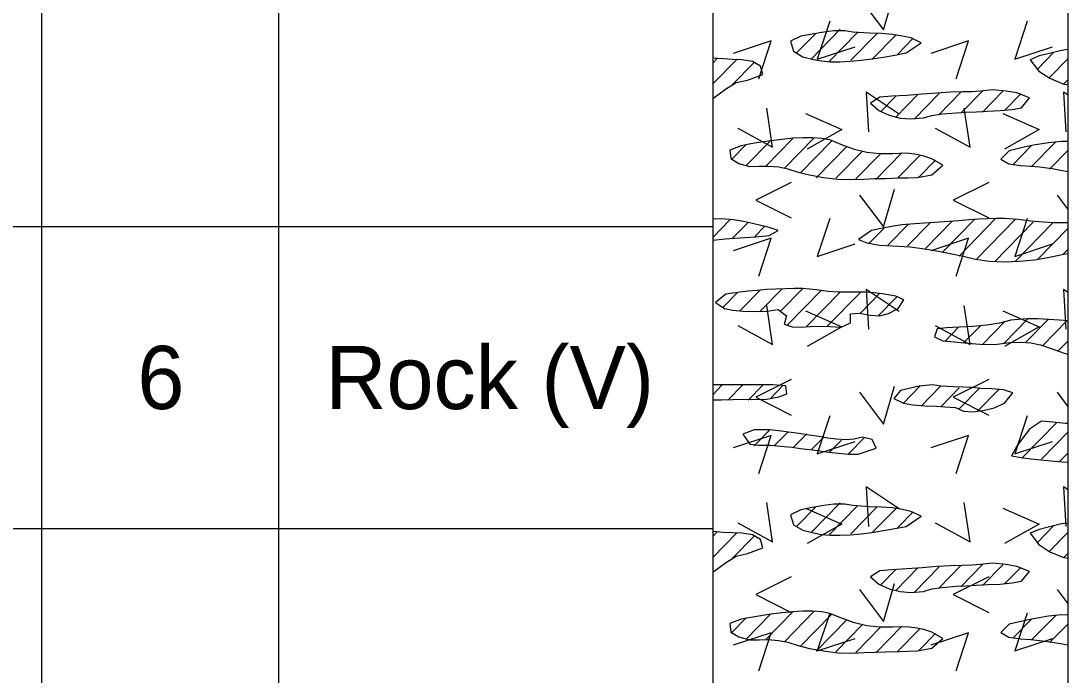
# Model space of a CAD drawing. Extents: x -0.01 to 0.83, y -0.63 to 1.27.
# Drawn here: x 0.7228 to 0.8333, y 0.1679 to 0.237 of the extents above; entities that cross this region are included whole.
import ezdxf

# ---------------------------------------------------------------- set-up
doc = ezdxf.new("R2010")
doc.units = 0

msp = doc.modelspace()

# ---------------------------------------------------------------- linework, layer by layer
for points in [[(0, 0), (0.83333, 0), (0.83333, 1.275), (0, 1.275)], [(0, 0), (0.83333, 0), (0.83333, 1.275), (0, 1.275)], [(0, 0), (0.83333, 0), (0.83333, 1.275), (0, 1.275)], [(0, 0), (0.83333, 0), (0.83333, 1.275), (0, 1.275)], [(0, 0), (0.83333, 0), (0.83333, 1.275), (0, 1.275)], [(0.81233, 0.23565), (0.81063, 0.23577), (0.80977, 0.23591), (0.8086, 0.23591), (0.80755, 0.23577), (0.80632, 0.23557), (0.80513, 0.23533), (0.80403, 0.23481), (0.80436, 0.23375), (0.80536, 0.23318), (0.80647, 0.23288), (0.8073, 0.23273), (0.80824, 0.23265), (0.80926, 0.23264), (0.81035, 0.2327), (0.81149, 0.2328), (0.81267, 0.23295), (0.81386, 0.23313), (0.81506, 0.23334), (0.81625, 0.23358), (0.81783, 0.23466), (0.81673, 0.23516), (0.81585, 0.23536), (0.8148, 0.23552), (0.81361, 0.23562)], [(0.83265, 0.23384), (0.83136, 0.23353), (0.83028, 0.23326), (0.82934, 0.23286), (0.83026, 0.23166), (0.83142, 0.2309), (0.83279, 0.23032), (0.83333, 0.23022), (0.83333, 0.23393)], [(0.79583, 0.22875), (0.79719, 0.22974), (0.79831, 0.23044), (0.79951, 0.23071), (0.80111, 0.23131), (0.80086, 0.23219), (0.80002, 0.23267), (0.79889, 0.23286), (0.79791, 0.23289), (0.79694, 0.23295), (0.79583, 0.23303)], [(0.82537, 0.22969), (0.82408, 0.22954), (0.82319, 0.22948), (0.82214, 0.22946), (0.82091, 0.22942), (0.81947, 0.22933), (0.81792, 0.22921), (0.81632, 0.22909), (0.81475, 0.229), (0.81348, 0.2289), (0.81247, 0.22826), (0.81337, 0.22749), (0.81444, 0.22699), (0.81561, 0.2267), (0.81675, 0.2266), (0.81807, 0.22671), (0.81896, 0.22698), (0.82003, 0.22713), (0.82157, 0.22725), (0.82253, 0.22731), (0.82362, 0.22737), (0.82483, 0.22743), (0.82618, 0.22749), (0.82745, 0.2276), (0.82842, 0.22778), (0.82927, 0.22883), (0.82791, 0.22935), (0.82679, 0.22955)], [(0.79885, 0.22378), (0.79763, 0.22332), (0.79773, 0.22242), (0.79859, 0.2219), (0.7997, 0.2216), (0.80074, 0.22161), (0.80165, 0.22163), (0.80281, 0.22154), (0.80377, 0.22134), (0.80486, 0.22099), (0.80606, 0.22069), (0.80751, 0.22042), (0.80905, 0.22023), (0.81052, 0.2202), (0.81177, 0.22026), (0.81289, 0.2203), (0.81408, 0.22033), (0.81553, 0.22037), (0.81642, 0.2204), (0.81745, 0.22043), (0.81897, 0.22071), (0.82011, 0.22174), (0.81896, 0.22241), (0.8181, 0.22268), (0.81717, 0.22287), (0.81626, 0.22298), (0.81479, 0.22292), (0.81343, 0.22292), (0.8121, 0.22307), (0.8108, 0.22338), (0.80953, 0.22384), (0.8082, 0.22439), (0.80736, 0.22455), (0.8064, 0.22462), (0.80536, 0.22462), (0.80427, 0.22456), (0.80314, 0.22445), (0.80201, 0.22431), (0.8009, 0.22414), (0.79984, 0.22396)], [(0.83263, 0.22423), (0.83126, 0.22409), (0.82969, 0.22382), (0.82883, 0.22365), (0.82712, 0.22324), (0.82623, 0.22237), (0.82708, 0.22188), (0.82831, 0.22169), (0.82941, 0.22163), (0.83033, 0.22154), (0.83165, 0.22136), (0.83253, 0.22121), (0.83333, 0.22107), (0.83333, 0.22422)], [(0.79583, 0.21382), (0.79715, 0.21393), (0.79814, 0.21401), (0.79922, 0.21408), (0.80039, 0.21417), (0.80179, 0.21429), (0.80275, 0.21481), (0.80179, 0.21515), (0.80091, 0.21536), (0.80003, 0.21558), (0.79909, 0.21579), (0.79803, 0.21595), (0.79677, 0.21605), (0.79583, 0.21603)], [(0.82816, 0.21158), (0.82978, 0.21174), (0.83137, 0.212), (0.8329, 0.21231), (0.83333, 0.21241), (0.83333, 0.21565), (0.83295, 0.21562), (0.83188, 0.21564), (0.83071, 0.21569), (0.82938, 0.2158), (0.82807, 0.21597), (0.82662, 0.21609), (0.82576, 0.21609), (0.82484, 0.21606), (0.82387, 0.21601), (0.82286, 0.21594), (0.82182, 0.21586), (0.82077, 0.21578), (0.81973, 0.2157), (0.81872, 0.21562), (0.81715, 0.21552), (0.81579, 0.21543), (0.81491, 0.2153), (0.81357, 0.21502), (0.8126, 0.21481), (0.81121, 0.21389), (0.8121, 0.21353), (0.81345, 0.21329), (0.81479, 0.21319), (0.81668, 0.21309), (0.81818, 0.21289), (0.81905, 0.21275), (0.82, 0.21257), (0.82107, 0.21235), (0.82225, 0.2121), (0.82357, 0.21181), (0.82501, 0.21158), (0.82656, 0.21151)], [(0.79708, 0.20659), (0.79794, 0.20642), (0.79904, 0.2063), (0.80028, 0.20627), (0.80156, 0.20632), (0.80274, 0.20648), (0.80361, 0.20582), (0.80338, 0.20492), (0.80422, 0.20465), (0.80517, 0.20463), (0.80613, 0.20469), (0.8072, 0.20472), (0.80818, 0.20469), (0.80939, 0.20461), (0.81037, 0.20508), (0.81038, 0.20603), (0.8113, 0.20609), (0.81244, 0.2059), (0.81346, 0.2058), (0.81438, 0.20605), (0.81539, 0.20659), (0.81601, 0.20751), (0.81517, 0.20788), (0.81374, 0.20815), (0.81285, 0.20825), (0.81187, 0.20831), (0.81, 0.20831), (0.8091, 0.20833), (0.808, 0.2084), (0.80678, 0.20856), (0.8053, 0.20869), (0.80443, 0.2087), (0.80349, 0.20868), (0.80251, 0.20864), (0.80152, 0.20858), (0.80054, 0.2085), (0.79959, 0.20841), (0.7987, 0.20831), (0.79722, 0.20809), (0.79614, 0.20721)], [(0.83241, 0.20537), (0.83129, 0.20544), (0.83017, 0.20548), (0.8291, 0.20548), (0.82811, 0.20544), (0.82728, 0.20535), (0.82608, 0.20505), (0.82476, 0.20483), (0.8233, 0.20469), (0.82183, 0.20461), (0.82051, 0.20455), (0.81951, 0.20445), (0.81922, 0.20358), (0.82013, 0.20317), (0.82097, 0.20311), (0.822, 0.20301), (0.82318, 0.20288), (0.82448, 0.2028), (0.82584, 0.20282), (0.82719, 0.20299), (0.82836, 0.20305), (0.8294, 0.20297), (0.83043, 0.20274), (0.83156, 0.20235), (0.83291, 0.20186), (0.83333, 0.20178), (0.83333, 0.2053)], [(0.79583, 0.19696), (0.79676, 0.19695), (0.79792, 0.19697), (0.79882, 0.19701), (0.79992, 0.19697), (0.80151, 0.19701), (0.80282, 0.19727), (0.80367, 0.19759), (0.80354, 0.19843), (0.80216, 0.19851), (0.79583, 0.19851)], [(0.81822, 0.19632), (0.81944, 0.19626), (0.82033, 0.19622), (0.82145, 0.19615), (0.82229, 0.19574), (0.82324, 0.19569), (0.82438, 0.1958), (0.82555, 0.19609), (0.82662, 0.19659), (0.82749, 0.19769), (0.82651, 0.19799), (0.82524, 0.19809), (0.82413, 0.19815), (0.82324, 0.19826), (0.82226, 0.19828), (0.82121, 0.1983), (0.81995, 0.1984), (0.81902, 0.19851), (0.81761, 0.19837), (0.81566, 0.19793), (0.81496, 0.19709), (0.81598, 0.1966), (0.81695, 0.19643)], [(0.83305, 0.19446), (0.83171, 0.19457), (0.83054, 0.19468), (0.82925, 0.19386), (0.82857, 0.19294), (0.82792, 0.19205), (0.82735, 0.19103), (0.82858, 0.1908), (0.82945, 0.1907), (0.83045, 0.19061), (0.83155, 0.19051), (0.83272, 0.19041), (0.83333, 0.19036), (0.83333, 0.19445)], [(0.80066, 0.19216), (0.80188, 0.19215), (0.80339, 0.19203), (0.80423, 0.19193), (0.8051, 0.19182), (0.806, 0.1917), (0.80692, 0.19158), (0.80784, 0.19146), (0.80875, 0.19135), (0.81014, 0.19121), (0.81119, 0.19122), (0.81222, 0.19157), (0.81308, 0.19185), (0.81267, 0.19275), (0.8116, 0.193), (0.81075, 0.1928), (0.80989, 0.19272), (0.80885, 0.1928), (0.80799, 0.19291), (0.80703, 0.19306), (0.806, 0.19322), (0.80492, 0.19339), (0.80384, 0.19354), (0.8028, 0.19368), (0.80182, 0.19377), (0.8002, 0.19378), (0.79901, 0.1933), (0.79974, 0.19226)], [(0.81233, 0.18565), (0.81063, 0.18577), (0.80977, 0.18591), (0.8086, 0.18591), (0.80755, 0.18577), (0.80632, 0.18557), (0.80513, 0.18533), (0.80403, 0.18481), (0.80436, 0.18375), (0.80536, 0.18318), (0.80647, 0.18288), (0.8073, 0.18273), (0.80824, 0.18265), (0.80926, 0.18264), (0.81035, 0.1827), (0.81149, 0.1828), (0.81267, 0.18295), (0.81386, 0.18313), (0.81506, 0.18334), (0.81625, 0.18358), (0.81783, 0.18466), (0.81673, 0.18516), (0.81585, 0.18536), (0.8148, 0.18552), (0.81361, 0.18562)], [(0.83265, 0.18384), (0.83136, 0.18353), (0.83028, 0.18326), (0.82934, 0.18286), (0.83026, 0.18166), (0.83142, 0.1809), (0.83279, 0.18032), (0.83333, 0.18022), (0.83333, 0.18393)], [(0.79583, 0.17875), (0.79719, 0.17974), (0.79831, 0.18044), (0.79951, 0.18071), (0.80111, 0.18131), (0.80086, 0.18219), (0.80002, 0.18267), (0.79889, 0.18286), (0.79791, 0.18289), (0.79694, 0.18295), (0.79583, 0.18303)], [(0.82537, 0.17969), (0.82408, 0.17954), (0.82319, 0.17948), (0.82214, 0.17946), (0.82091, 0.17942), (0.81947, 0.17933), (0.81792, 0.17921), (0.81632, 0.17909), (0.81475, 0.179), (0.81348, 0.1789), (0.81247, 0.17826), (0.81337, 0.17749), (0.81444, 0.17699), (0.81561, 0.1767), (0.81675, 0.1766), (0.81807, 0.17671), (0.81896, 0.17698), (0.82003, 0.17713), (0.82157, 0.17725), (0.82253, 0.17731), (0.82362, 0.17737), (0.82483, 0.17743), (0.82618, 0.17749), (0.82745, 0.1776), (0.82842, 0.17778), (0.82927, 0.17883), (0.82791, 0.17935), (0.82679, 0.17955)], [(0.79885, 0.17378), (0.79763, 0.17332), (0.79773, 0.17242), (0.79859, 0.1719), (0.7997, 0.1716), (0.80074, 0.17161), (0.80165, 0.17163), (0.80281, 0.17154), (0.80377, 0.17134), (0.80486, 0.17099), (0.80606, 0.17069), (0.80751, 0.17042), (0.80905, 0.17023), (0.81052, 0.1702), (0.81177, 0.17026), (0.81289, 0.1703), (0.81408, 0.17033), (0.81553, 0.17037), (0.81642, 0.1704), (0.81745, 0.17043), (0.81897, 0.17071), (0.82011, 0.17174), (0.81896, 0.17241), (0.8181, 0.17268), (0.81717, 0.17287), (0.81626, 0.17298), (0.81479, 0.17292), (0.81343, 0.17292), (0.8121, 0.17307), (0.8108, 0.17338), (0.80953, 0.17384), (0.8082, 0.17439), (0.80736, 0.17455), (0.8064, 0.17462), (0.80536, 0.17462), (0.80427, 0.17456), (0.80314, 0.17445), (0.80201, 0.17431), (0.8009, 0.17414), (0.79984, 0.17396)], [(0.83263, 0.17423), (0.83126, 0.17409), (0.82969, 0.17382), (0.82883, 0.17365), (0.82712, 0.17324), (0.82623, 0.17237), (0.82708, 0.17188), (0.82831, 0.17169), (0.82941, 0.17163), (0.83033, 0.17154), (0.83165, 0.17136), (0.83253, 0.17121), (0.83333, 0.17107), (0.83333, 0.17422)]]:
    msp.add_lwpolyline(points, close=True)
for points in [[(0.725, 1.22083), (0.725, -0.62183)], [(0.75, 1.22083), (0.75, -0.62183)], [(0.75, 1.22083), (0.75, -0.62183)], [(0.79583, 1.22083), (0.79583, -0.62183)], [(0.725, 1.20833), (0.725, -0.62183)], [(0.83333, -0.62183), (0.83333, 1.13843)], [(0.81134, 0.23941), (0.81384, 0.23603), (0.81503, 0.24003)], [(0.80818, 0.23692), (0.80687, 0.23292), (0.81087, 0.23423)], [(0.82901, 0.23692), (0.8277, 0.23292), (0.8317, 0.23423)], [(0.80465, 0.23354), (0.80667, 0.23561)], [(0.80626, 0.23297), (0.80928, 0.23607)], [(0.80809, 0.23264), (0.81111, 0.23574)], [(0.81041, 0.2328), (0.81318, 0.23564)], [(0.81264, 0.23288), (0.81518, 0.23548)], [(0.80069, 0.23084), (0.802, 0.23484), (0.798, 0.23352)], [(0.81536, 0.23345), (0.81699, 0.23512)], [(0.82152, 0.23084), (0.82284, 0.23484), (0.81884, 0.23352)], [(0.8301, 0.23188), (0.83184, 0.23366)], [(0.7963, 0.23299), (0.79583, 0.23251)], [(0.79834, 0.23286), (0.79583, 0.2303)], [(0.79786, 0.23016), (0.80023, 0.23259)], [(0.83131, 0.2309), (0.83333, 0.23298)], [(0.83285, 0.23027), (0.83333, 0.23076)], [(0.81551, 0.22711), (0.81201, 0.22942), (0.81226, 0.22523)], [(0.81519, 0.22906), (0.81354, 0.22736)], [(0.81514, 0.2268), (0.81748, 0.22919)], [(0.81709, 0.22658), (0.81974, 0.2293)], [(0.8197, 0.22704), (0.82203, 0.22943)], [(0.82202, 0.2272), (0.8243, 0.22954)], [(0.82431, 0.22733), (0.82644, 0.22953)], [(0.82663, 0.2275), (0.82834, 0.22925)], [(0.83333, 0.2291), (0.83284, 0.22942), (0.83309, 0.22523)], [(0.79847, 0.22563), (0.80215, 0.22363), (0.80153, 0.22775)], [(0.8193, 0.22563), (0.82299, 0.22363), (0.82236, 0.22775)], [(0.80562, 0.22717), (0.80946, 0.22549), (0.80581, 0.22343)], [(0.82645, 0.22717), (0.83029, 0.22549), (0.82664, 0.22343)], [(0.79933, 0.22165), (0.80195, 0.22434)], [(0.80142, 0.22158), (0.8043, 0.22454)], [(0.80653, 0.22461), (0.8034, 0.2214)], [(0.79938, 0.22392), (0.79786, 0.22237)], [(0.80506, 0.22089), (0.8084, 0.22431)], [(0.80997, 0.22371), (0.80675, 0.2204)], [(0.82751, 0.22176), (0.82945, 0.22375)], [(0.83203, 0.22418), (0.82949, 0.22158)], [(0.83138, 0.2213), (0.83333, 0.2233)], [(0.81164, 0.2232), (0.80884, 0.22034)], [(0.81353, 0.22293), (0.81094, 0.22027)], [(0.81303, 0.22021), (0.81579, 0.22303)], [(0.81534, 0.22036), (0.81768, 0.22276)], [(0.8176, 0.22047), (0.81934, 0.22225)], [(0.83333, 0.22108), (0.83333, 0.22109)], [(0.80412, 0.21991), (0.80038, 0.21804), (0.80412, 0.21616)], [(0.82496, 0.21991), (0.82121, 0.21804), (0.82496, 0.21616)], [(0.81134, 0.21857), (0.81384, 0.2152), (0.81503, 0.2192)], [(0.83217, 0.21857), (0.83333, 0.21701)], [(0.79765, 0.21594), (0.79583, 0.21407)], [(0.7996, 0.21572), (0.79786, 0.21394)], [(0.80818, 0.21608), (0.80687, 0.21208), (0.81087, 0.2134)], [(0.8143, 0.21326), (0.8165, 0.21551)], [(0.8164, 0.21319), (0.81879, 0.21565)], [(0.81829, 0.21292), (0.82114, 0.21584)], [(0.82004, 0.2125), (0.82346, 0.216)], [(0.82569, 0.21608), (0.82184, 0.21213)], [(0.82775, 0.21598), (0.8237, 0.21183)], [(0.82964, 0.2157), (0.82557, 0.21153)], [(0.82901, 0.21608), (0.8277, 0.21208), (0.8317, 0.2134)], [(0.83173, 0.21563), (0.82774, 0.21154)], [(0.70417, 0.21525), (0.725, 0.21525)], [(0.725, 0.21525), (0.75, 0.21525)], [(0.75, 0.21525), (0.79583, 0.21525)], [(0.8013, 0.21524), (0.80027, 0.21419)], [(0.81392, 0.21508), (0.81235, 0.21348)], [(0.83333, 0.21506), (0.83012, 0.21176)], [(0.80069, 0.21), (0.802, 0.214), (0.798, 0.21269)], [(0.82152, 0.21), (0.82284, 0.214), (0.81884, 0.21269)], [(0.83281, 0.21231), (0.83333, 0.21284)], [(0.79844, 0.20828), (0.79691, 0.20671)], [(0.79871, 0.20634), (0.80085, 0.20853)], [(0.80083, 0.20629), (0.80311, 0.20863)], [(0.80534, 0.20871), (0.80299, 0.20629)], [(0.80367, 0.20478), (0.80732, 0.20852)], [(0.80571, 0.20466), (0.80924, 0.20828)], [(0.81142, 0.20829), (0.80785, 0.20464)], [(0.81141, 0.20607), (0.81348, 0.20819)], [(0.81551, 0.20628), (0.81201, 0.20859), (0.81226, 0.2044)], [(0.81528, 0.20783), (0.81331, 0.20581)], [(0.83333, 0.20827), (0.83284, 0.20859), (0.83309, 0.2044)], [(0.79847, 0.20479), (0.80215, 0.20279), (0.80153, 0.20692)], [(0.8193, 0.20479), (0.82299, 0.20279), (0.82236, 0.20692)], [(0.80562, 0.20634), (0.80946, 0.20466), (0.80581, 0.20259)], [(0.82645, 0.20634), (0.83029, 0.20466), (0.82664, 0.20259)], [(0.82035, 0.20315), (0.82176, 0.2046)], [(0.82233, 0.20298), (0.82408, 0.20476)], [(0.82433, 0.20281), (0.82666, 0.2052)], [(0.82909, 0.20548), (0.82656, 0.20289)], [(0.82885, 0.20301), (0.83122, 0.20544)], [(0.83325, 0.20531), (0.83065, 0.20265)], [(0.83333, 0.20318), (0.83227, 0.20209)], [(0.80412, 0.19908), (0.80038, 0.19721), (0.80412, 0.19533)], [(0.82496, 0.19908), (0.82121, 0.19721), (0.82496, 0.19533)], [(0.79583, 0.19748), (0.79681, 0.19848)], [(0.79898, 0.1985), (0.79747, 0.19695)], [(0.80116, 0.19852), (0.79959, 0.19691)], [(0.80328, 0.19848), (0.80188, 0.19704)], [(0.81134, 0.19774), (0.81384, 0.19437), (0.81503, 0.19837)], [(0.8177, 0.19837), (0.81596, 0.19659)], [(0.81988, 0.19839), (0.81785, 0.19632)], [(0.82185, 0.1982), (0.81997, 0.19628)], [(0.824, 0.19819), (0.82178, 0.19591)], [(0.82601, 0.19803), (0.82378, 0.19576)], [(0.83217, 0.19774), (0.83333, 0.19618)], [(0.80818, 0.19525), (0.80687, 0.19125), (0.81087, 0.19256)], [(0.82901, 0.19525), (0.8277, 0.19125), (0.8317, 0.19256)], [(0.83217, 0.19459), (0.82844, 0.19077)], [(0.80188, 0.19382), (0.8002, 0.19209)], [(0.8038, 0.19357), (0.80237, 0.19211)], [(0.83333, 0.19357), (0.83052, 0.19069)], [(0.80069, 0.18917), (0.802, 0.19317), (0.798, 0.19186)], [(0.80575, 0.19335), (0.80429, 0.19186)], [(0.80758, 0.19302), (0.80627, 0.19168)], [(0.80941, 0.19269), (0.80816, 0.1914)], [(0.81188, 0.193), (0.81016, 0.19124)], [(0.82152, 0.18917), (0.82284, 0.19317), (0.81884, 0.19186)], [(0.83333, 0.19136), (0.83245, 0.19045)], [(0.81551, 0.18544), (0.81201, 0.18776), (0.81226, 0.18357)], [(0.83333, 0.18743), (0.83284, 0.18776), (0.83309, 0.18357)], [(0.79847, 0.18396), (0.80215, 0.18196), (0.80153, 0.18609)], [(0.80626, 0.18297), (0.80928, 0.18607)], [(0.80809, 0.18264), (0.81111, 0.18574)], [(0.8193, 0.18396), (0.82299, 0.18196), (0.82236, 0.18609)], [(0.80465, 0.18354), (0.80667, 0.18561)], [(0.80562, 0.18551), (0.80946, 0.18382), (0.80581, 0.18176)], [(0.81041, 0.1828), (0.81318, 0.18564)], [(0.81264, 0.18288), (0.81518, 0.18548)], [(0.81536, 0.18345), (0.81699, 0.18512)], [(0.82645, 0.18551), (0.83029, 0.18382), (0.82664, 0.18176)], [(0.8301, 0.18188), (0.83184, 0.18366)], [(0.70417, 0.18336), (0.725, 0.18336)], [(0.725, 0.18336), (0.75, 0.18336)], [(0.75, 0.18336), (0.79583, 0.18336)], [(0.7963, 0.18299), (0.79583, 0.18251)], [(0.79834, 0.18286), (0.79583, 0.1803)], [(0.79786, 0.18016), (0.80023, 0.18259)], [(0.83131, 0.1809), (0.83333, 0.18298)], [(0.83285, 0.18027), (0.83333, 0.18076)], [(0.81519, 0.17906), (0.81354, 0.17736)], [(0.81514, 0.1768), (0.81748, 0.17919)], [(0.81709, 0.17658), (0.81974, 0.1793)], [(0.8197, 0.17704), (0.82203, 0.17943)], [(0.82202, 0.1772), (0.8243, 0.17954)], [(0.82431, 0.17733), (0.82644, 0.17953)], [(0.82663, 0.1775), (0.82834, 0.17925)], [(0.80412, 0.17825), (0.80038, 0.17637), (0.80412, 0.1745)], [(0.82496, 0.17825), (0.82121, 0.17637), (0.82496, 0.1745)], [(0.81134, 0.17691), (0.81384, 0.17353), (0.81503, 0.17753)], [(0.83217, 0.17691), (0.83333, 0.17535)], [(0.80653, 0.17461), (0.8034, 0.1714)], [(0.79938, 0.17392), (0.79786, 0.17237)], [(0.79933, 0.17165), (0.80195, 0.17434)], [(0.80142, 0.17158), (0.8043, 0.17454)], [(0.80506, 0.17089), (0.8084, 0.17431)], [(0.80997, 0.17371), (0.80675, 0.1704)], [(0.80818, 0.17442), (0.80687, 0.17042), (0.81087, 0.17173)], [(0.82751, 0.17176), (0.82945, 0.17375)], [(0.82901, 0.17442), (0.8277, 0.17042), (0.8317, 0.17173)], [(0.83203, 0.17418), (0.82949, 0.17158)], [(0.81164, 0.1732), (0.80884, 0.17034)], [(0.81353, 0.17293), (0.81094, 0.17027)], [(0.81303, 0.17021), (0.81579, 0.17303)], [(0.81534, 0.17036), (0.81768, 0.17276)], [(0.83138, 0.1713), (0.83333, 0.1733)], [(0.80069, 0.16834), (0.802, 0.17234), (0.798, 0.17102)], [(0.8176, 0.17047), (0.81934, 0.17225)], [(0.82152, 0.16834), (0.82284, 0.17234), (0.81884, 0.17102)], [(0.83333, 0.17108), (0.83333, 0.17109)]]:
    msp.add_lwpolyline(points)

# ---------------------------------------------------------------- texts
for s, height, p in [('6', 0.00667, (0.73512, 0.19597)), ('Rock (V)', 0.006667, (0.75497, 0.19597))]:
    msp.add_text(s, height=height).set_placement(p)

doc.saveas('drawing.dxf')
